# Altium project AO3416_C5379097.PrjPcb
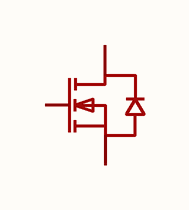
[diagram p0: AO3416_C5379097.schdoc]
1 sheet, 1 parts. Net scope: global (net labels, ports and power ports of the same name join across sheets).

## Sheet AO3416_C5379097.schdoc
size 127 x 101 mm

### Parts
Q?  ao3416_c5379097  [SOT-23-3_L2.9-W1.6-P1.90-LS2.8-BR]  (value not drawn)

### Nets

Not connected (* = marked no-connect by the designer): Q? 1(G) 2(S) 3(D)

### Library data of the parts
Q? = ao3416_c5379097: 数量:1个N沟道;漏源电压(Vdss):20V;连续漏极电流(Id):6.5A;导通电阻(RDS(on)):16mΩ@4.5V;耗散功率(Pd):1.56W;阈值电压(Vgs(th)):600mV;; Manufacturer: MSKSEMI(美森科); ManufacturerPart: AO3416; AddInBom: yes; ModelId: 89cb27a44ab2466697082bb9fd73a7d0; ModelName: SOT-23-3L_L2.9-W1.6-H1.1-LS2.8-P0.95; ModelTransform: 114.173,110.236,0,90,0,0,0,0,0; Number: 1个N沟道; Drain to Source Voltage: 20V; Current - Continuous Drain(Id): 6.5A; Pd - Power Dissipation: 1.56W; Gate Threshold Voltage (Vgs(th)): 600mV; Gate Charge(Qg): 5.8nC@4.5V; Input Capacitance(Ciss): 600pF; Reverse Transfer Capacitance (Crss@Vds): 45pF; Output Capacitance(Coss): 70pF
